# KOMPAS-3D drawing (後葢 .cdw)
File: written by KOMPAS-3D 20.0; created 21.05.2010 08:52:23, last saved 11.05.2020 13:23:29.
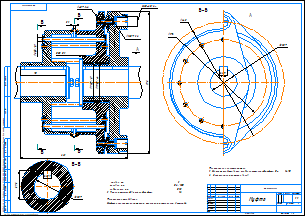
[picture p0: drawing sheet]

Sheet 1: A2, landscape

Document properties: Полное имя файла: C:\Users\Пользователь\Downloads\Муфта.cdw

Title block, sheet 1: Наименование: Муфта; designation: ДМ 413-01.00.11; scale: 1:1; Количество листов документа: 1; Форматы листов документа: A2; stored path: F:\учеба\ДМ\Курсачи ДМ\Куча курсачей\МСХ-61\Храмеев, МСХ-61, вар. 3\Муфта.cdw

Views: Вид 1, Вид 2, Вид 3
Referenced files in /: f7, p6, js6, k6
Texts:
  JS9
  js9
Dimensions and other numbers on the sheet: 16; 57,5; 53; 245; 176; 90; 71; 79; 0,05...0,1; 8; 5,1; 278; 221; 4; -6H/6g; 20; 12; 1:1; 1

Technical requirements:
  Техническая характеристика
  Момент срабатывания предохранительной муфты, Нм.................1490
  Допускаемое смещение валов
  осевое, мм ..................................................................................................................................3
  угловое, мм...........................................................................................................................0,6/100
  радиальное, мм........................................................................................................................0,15
  Число стержней в упругой муфте...................................................................12
  Технические требования
  Муфту заполнить пластичным смазочным материалом Литол-24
